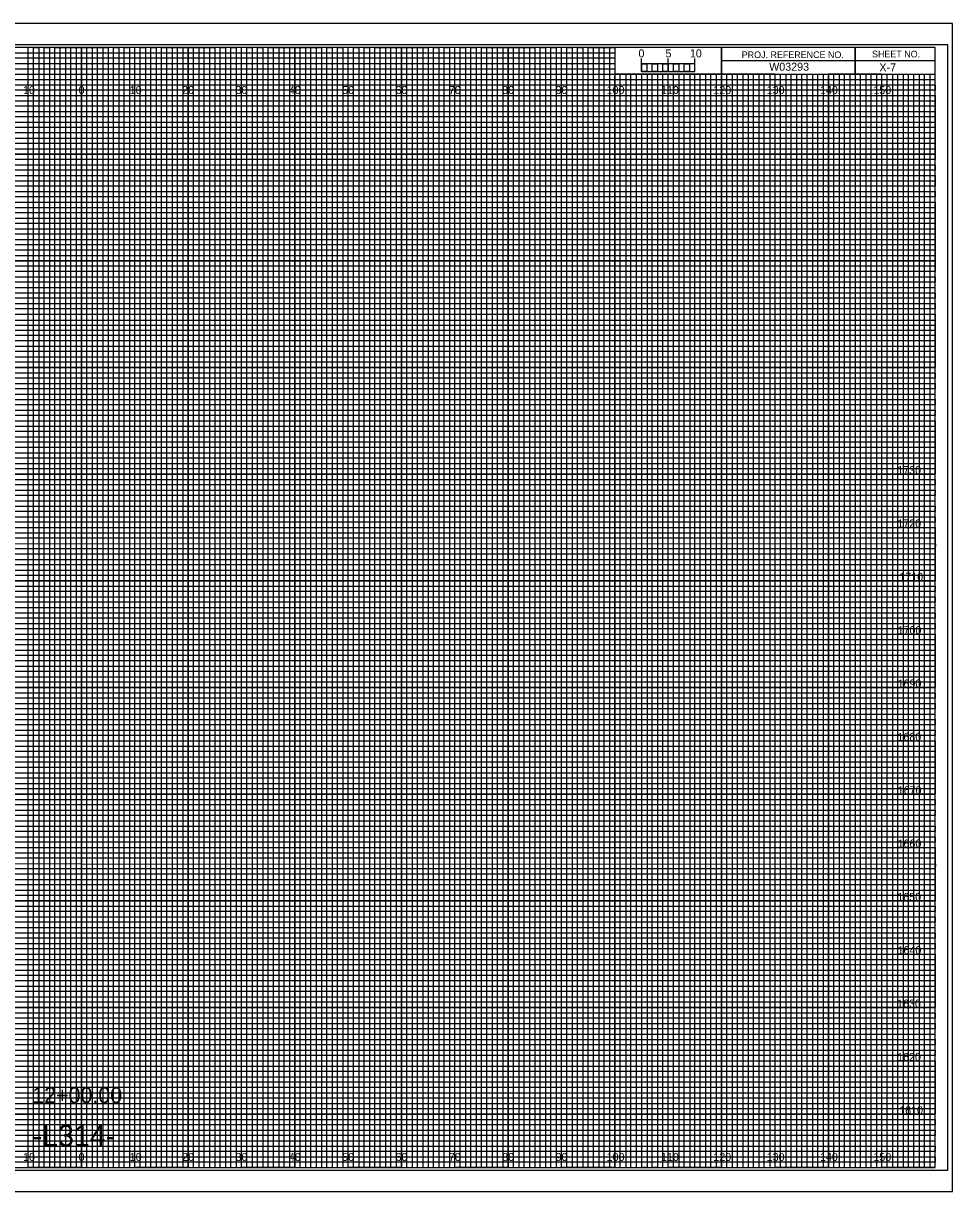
# Model space of a CAD drawing. Extents: x -13 to 323, y 435 to 654.
# Drawn here: x 149.1 to 323.3, y 435.5 to 654.5 of the extents above; entities that cross this region are included whole.
import ezdxf

# ---------------------------------------------------------------- set-up
doc = ezdxf.new("R2010")
doc.units = 0
for name, color, linetype in [('Exist Cross Section Cell', 7, 'Continuous'), ('Exist Horizontal Alignment', 7, 'Continuous'), ('Exist XS Center Line Elevation Label', 7, 'Continuous'), ('Exist XS Ground Line', 7, 'Continuous'), ('Prop Study Area', 7, 'Continuous'), ('Prop XS Finish Grade', 7, 'Continuous'), ('Prop XS Finish Grade Earthwork', 7, 'Continuous'), ('Prop XS Finish Grade Pavement', 7, 'Continuous'), ('Prop XS Pvmt Edge Slope', 7, 'Continuous'), ('Prop XS SE Text', 7, 'Continuous'), ('Prop XS Side Slope Text', 7, 'Continuous'), ('Prop XS Subgrade Earthwork', 7, 'Continuous'), ('Prop XSC Text', 7, 'Continuous'), ('Scratch_Level_0', 7, 'Continuous'), ('Scratch_Level_5', 7, 'Continuous'), ('Typical Guardrail CELL', 7, 'Continuous')]:
    doc.layers.add(name, color=color, linetype=linetype)

msp = doc.modelspace()

# ---------------------------------------------------------------- linework, layer by layer
at = {"layer": 'Exist Cross Section Cell'}
for p, q in [((265, 645.49), (265, 647.9)), ((265, 646.9), (265, 647.9)), ((270, 645.49), (270, 647.9)), ((275, 645.49), (275, 647.9)), ((275, 646.9), (275, 647.9))]:
    msp.add_line(p, q, dxfattribs=at)
for points in [[(275, 646.9), (265, 646.9), (265, 645.49), (275, 645.49)], [(265, 646.9), (266, 646.9), (266, 645.49), (265, 645.49)], [(267, 646.9), (268, 646.9), (268, 645.49), (267, 645.49)], [(269, 646.9), (270, 646.9), (270, 645.49), (269, 645.49)], [(271, 646.9), (272, 646.9), (272, 645.49), (271, 645.49)], [(273, 646.9), (274, 646.9), (274, 645.49), (273, 645.49)]]:
    msp.add_lwpolyline(points, close=True, dxfattribs=at)
at = {"layer": 'Exist Horizontal Alignment'}
for points in [[(145, 440), (155, 440), (155, 650), (165, 650), (165, 440), (175, 440), (175, 650), (185, 650), (185, 440), (195, 440), (195, 650), (205, 650), (205, 440), (215, 440), (215, 650), (225, 650), (225, 440), (235, 440), (235, 650), (245, 650), (245, 440), (255, 440), (255, 650), (259.93, 650), (260, 650), (260, 645), (264.99, 645), (264.99, 440), (275, 440), (275, 645), (285, 645), (285, 440), (295, 440), (295, 645), (305, 645), (305, 440), (315, 440), (315, 645)], [(0, 645), (275, 645)], [(0, 625), (320, 625), (320, 635), (0, 635)], [(0, 605), (320, 605), (320, 615), (0, 615)], [(0, 585), (320, 585), (320, 595), (0, 595)], [(0, 565), (320, 565), (320, 575), (0, 575)], [(0, 545), (320, 545), (320, 555), (0, 555)], [(0, 525), (320, 525), (320, 535), (0, 535)], [(0, 505), (320, 505), (320, 515), (0, 515)], [(0, 485), (320, 485), (320, 495), (0, 495)], [(0, 465), (320, 465), (320, 475), (0, 475)], [(0, 445), (320, 445), (320, 455), (0, 455)]]:
    msp.add_lwpolyline(points, dxfattribs=at)
at = {"layer": 'Exist XS Center Line Elevation Label'}
for p, q in [((267, 645), (266.01, 645)), ((266.01, 645), (266.01, 440)), ((267, 440), (267, 645)), ((269, 645), (268, 645)), ((268, 645), (268, 440)), ((269, 440), (269, 645)), ((266.01, 440), (265, 440)), ((268, 440), (267, 440))]:
    msp.add_line(p, q, dxfattribs=at)
for points in [[(150, 440), (151, 440), (151, 650), (152, 650), (152, 440)], [(152, 440), (153, 440), (153, 650), (154, 650), (154, 440)], [(155, 440), (156, 440), (156, 650), (157, 650), (157, 440)], [(157, 440), (158, 440), (158, 650), (159, 650), (159, 440)], [(160, 440), (161, 440), (161, 650), (162, 650), (162, 440)], [(162, 440), (163, 440), (163, 650), (164, 650), (164, 440)], [(165, 440), (166, 440), (166, 650), (167, 650), (167, 440)], [(167, 440), (168, 440), (168, 650), (169, 650), (169, 440)], [(170, 440), (171, 440), (171, 650), (172, 650), (172, 440)], [(172, 440), (173, 440), (173, 650), (174, 650), (174, 440)], [(175, 440), (176, 440), (176, 650), (177, 650), (177, 440)], [(177, 440), (178, 440), (178, 650), (179, 650), (179, 440)], [(180, 440), (181, 440), (181, 650), (182, 650), (182, 440)], [(182, 440), (183, 440), (183, 650), (184, 650), (184, 440)], [(185, 440), (186, 440), (186, 650), (187, 650), (187, 440)], [(187, 440), (188, 440), (188, 650), (189, 650), (189, 440)], [(190, 440), (191, 440), (191, 650), (192, 650), (192, 440)], [(192, 440), (193, 440), (193, 650), (194, 650), (194, 440)], [(195, 440), (196, 440), (196, 650), (197, 650), (197, 440)], [(197, 440), (198, 440), (198, 650), (199, 650), (199, 440)], [(200, 440), (201, 440), (201, 650), (202, 650), (202, 440)], [(202, 440), (203, 440), (203, 650), (204, 650), (204, 440)], [(205, 440), (206, 440), (206, 650), (207, 650), (207, 440)], [(207, 440), (208, 440), (208, 650), (209, 650), (209, 440)], [(210, 440), (211, 440), (211, 650), (212, 650), (212, 440)], [(212, 440), (213, 440), (213, 650), (214, 650), (214, 440)], [(215, 440), (216, 440), (216, 650), (217, 650), (217, 440)], [(217, 440), (218, 440), (218, 650), (219, 650), (219, 440)], [(220, 440), (221, 440), (221, 650), (222, 650), (222, 440)], [(222, 440), (223, 440), (223, 650), (224, 650), (224, 440)], [(225, 440), (226, 440), (226, 650), (227, 650), (227, 440)], [(227, 440), (228, 440), (228, 650), (229, 650), (229, 440)], [(230, 440), (231, 440), (231, 650), (232, 650), (232, 440)], [(232, 440), (233, 440), (233, 650), (234, 650), (234, 440)], [(235, 440), (236, 440), (236, 650), (237, 650), (237, 440)], [(237, 440), (238, 440), (238, 650), (239, 650), (239, 440)], [(240, 440), (241, 440), (241, 650), (242, 650), (242, 440)], [(242, 440), (243, 440), (243, 650), (244, 650), (244, 440)], [(245, 440), (246, 440), (246, 650), (247, 650), (247, 440)], [(247, 440), (248, 440), (248, 650), (249, 650), (249, 440)], [(250, 440), (251, 440), (251, 650), (252, 650), (252, 440)], [(252, 440), (253, 440), (253, 650), (254, 650), (254, 440)], [(255, 440), (256, 440), (256, 650), (257, 650), (257, 440)], [(257, 440), (258, 440), (258, 650), (259, 650), (259, 440)], [(260, 440), (261, 440), (261, 645), (262.02, 645), (262.02, 440)], [(262, 440), (263, 440), (263, 645), (263.99, 645), (263.99, 440)], [(270, 440), (270.98, 440), (270.98, 645), (272, 645), (272, 440)], [(272, 440), (273, 440), (273, 645), (274.05, 645), (274.05, 440)], [(275, 440), (276, 440), (276, 645), (277, 645), (277, 440)], [(277, 440), (278, 440), (278, 645), (279, 645), (279, 440)], [(280, 440), (281, 440), (281, 645), (282, 645), (282, 440)], [(282, 440), (283, 440), (283, 645), (284, 645), (284, 440)], [(285, 440), (286, 440), (286, 645), (287, 645), (287, 440)], [(287, 440), (288, 440), (288, 645), (289, 645), (289, 440)], [(290, 440), (291, 440), (291, 645), (292, 645), (292, 440)], [(292, 440), (293, 440), (293, 645), (294, 645), (294, 440)], [(295, 440), (296, 440), (296, 645), (297, 645), (297, 440)], [(297, 440), (298, 440), (298, 645), (299, 645), (299, 440)], [(300, 440), (301, 440), (301, 645), (302, 645), (302, 440)], [(302, 440), (303, 440), (303, 645), (304, 645), (304, 440)], [(305, 440), (306, 440), (306, 645), (307, 645), (307, 440)], [(307, 440), (308, 440), (308, 645), (309, 645), (309, 440)], [(310, 440), (311, 440), (311, 645), (312, 645), (312, 440)], [(312, 440), (313, 440), (313, 645), (314, 645), (314, 440)], [(315, 440), (316, 440), (316, 645), (317, 645), (317, 440)], [(317, 440), (318, 440), (318, 645), (319, 645), (319, 440)]]:
    msp.add_lwpolyline(points, dxfattribs=at)
at = {"layer": 'Exist XS Ground Line'}
for p, q in [((305, 650), (305, 645)), ((305, 645), (305, 650)), ((280, 647.5), (280, 645)), ((320, 647.49), (280, 647.49)), ((280, 645), (320, 645))]:
    msp.add_line(p, q, dxfattribs=at)
for points in [[(320, 650), (0, 650), (0, 440), (320, 440)], [(280, 650), (260, 650), (260, 645.03), (280, 645.03)], [(320, 650), (280, 650), (280, 645), (320, 645)]]:
    msp.add_lwpolyline(points, close=True, dxfattribs=at)
at = {"layer": 'Prop XS Finish Grade'}
msp.add_lwpolyline([(-10.8, 439.5), (322.4, 439.5), (322.4, 650.5), (-10.8, 650.5)], close=True, dxfattribs=at)
at = {"layer": 'Prop XS Finish Grade Pavement'}
msp.add_lwpolyline([(-13.4, 435.5), (323.3, 435.5), (323.3, 654.5), (-13.4, 654.5)], close=True, dxfattribs=at)
at = {"layer": 'Prop XS Pvmt Edge Slope'}
for p, q in [((323.3, 654.5), (-13.4, 654.5)), ((-13.4, 435.5), (323.3, 435.5))]:
    msp.add_line(p, q, dxfattribs=at)
at = {"layer": 'Scratch_Level_0'}
for p, q in [((150, 650), (140, 650)), ((150, 440), (150, 650)), ((170, 650), (160, 650)), ((160, 650), (160, 440)), ((170, 440), (170, 650)), ((190, 650), (180, 650)), ((180, 650), (180, 440)), ((190, 440), (190, 650)), ((210, 650), (200, 650)), ((200, 650), (200, 440)), ((210, 440), (210, 650)), ((230, 650), (220, 650)), ((220, 650), (220, 440)), ((230, 440), (230, 650)), ((250, 650), (240, 650)), ((240, 650), (240, 440)), ((250, 440), (250, 650)), ((260, 650), (260, 440)), ((270, 440), (270, 645)), ((290, 645), (280, 645)), ((280, 645), (280, 440)), ((290, 440), (290, 645)), ((310, 645), (300, 645)), ((300, 645), (300, 440)), ((310, 440), (310, 645)), ((160, 440), (150, 440)), ((180, 440), (170, 440)), ((200, 440), (190, 440)), ((220, 440), (210, 440)), ((240, 440), (230, 440)), ((260, 440), (250, 440)), ((280, 440), (270, 440)), ((300, 440), (290, 440)), ((320, 440), (310, 440)), ((320, 440), (320, 440))]:
    msp.add_line(p, q, dxfattribs=at)
for points in [[(0, 640), (320, 640), (320, 630), (0, 630)], [(0, 620), (320, 620), (320, 610), (0, 610)], [(0, 600), (320, 600), (320, 590), (0, 590)], [(0, 580), (320, 580), (320, 570), (0, 570)], [(0, 560), (320, 560), (320, 550), (0, 550)], [(0, 540), (320, 540), (320, 530), (0, 530)], [(0, 520), (320, 520), (320, 510), (0, 510)], [(0, 500), (320, 500), (320, 490), (0, 490)], [(0, 480), (320, 480), (320, 470), (0, 470)], [(0, 460), (320, 460), (320, 450), (0, 450)]]:
    msp.add_lwpolyline(points, dxfattribs=at)
at = {"layer": 'Scratch_Level_5'}
for p, q in [((0, 649), (260, 649)), ((260, 649), (260, 647.98)), ((260, 647.98), (0, 647.98)), ((0, 647), (260, 647)), ((260, 647), (260, 645.89)), ((260, 645.89), (0, 645.89)), ((0, 644), (320, 644))]:
    msp.add_line(p, q, dxfattribs=at)
for points in [[(0, 643), (270, 643), (320, 643), (320, 642), (0, 642)], [(0, 641), (320, 641), (320, 639), (0, 639)], [(0, 638), (320, 638), (320, 637), (0, 636.98)], [(0, 636), (320, 636), (320, 634), (0, 634)], [(0, 633), (320, 633), (320, 632), (0, 632)], [(0, 631), (320, 631), (320, 629), (0, 629)], [(0, 628), (320, 628), (320, 627), (0, 627)], [(0, 626), (320, 626), (320, 624), (0, 624)], [(0, 623), (320, 623), (320, 622), (0, 622)], [(0, 621), (320, 621), (320, 619), (0, 619)], [(0, 618), (320, 618), (320, 617), (0, 617)], [(0, 616), (320, 616), (320, 613.95), (320, 613), (320, 612), (0, 612)], [(0, 614), (320, 614), (320, 613), (0, 613)], [(0, 611), (320, 611), (320, 609), (0, 609.03)], [(0, 609.03), (320, 609), (320, 608), (0, 608)], [(0, 607), (320, 607), (320, 606), (0, 606)], [(0, 604), (320, 604), (320, 603), (0, 603)], [(0, 602), (320, 602), (320, 601), (0, 601)], [(-0.07, 598.89), (320, 598.89), (320, 597.88), (-0.07, 597.88)], [(0, 597), (320, 597), (320, 596), (0, 596)], [(0, 594), (320, 594), (320, 593), (0, 593)], [(0, 592), (320, 592), (320, 591), (0, 591)], [(0, 589), (320, 589), (320, 588), (0, 588)], [(0, 587), (320, 587), (320, 586), (0, 586)], [(0, 584), (320, 584), (320, 583), (0, 583)], [(0, 582), (320, 582), (320, 581), (0, 581)], [(0, 579), (320, 579), (319.99, 577.98), (0, 578)], [(0, 577), (320, 577), (320, 576), (0, 576)], [(0, 574), (320, 574), (320, 573), (0, 573)], [(0, 572), (320, 572), (320, 571), (0, 571)], [(0, 569), (320, 569), (320, 568), (0, 568)], [(0, 567), (320, 567), (320, 566), (0, 566)], [(0, 564), (320, 564), (320, 563), (0, 563)], [(0, 562), (320, 562), (320, 561), (0, 561)], [(0, 559), (320, 559), (320, 558), (0, 558)], [(0, 556.99), (320.07, 556.91), (320, 556), (0, 556)], [(0, 554), (320, 554), (320, 553), (0, 553)], [(0, 552), (320, 552), (320, 551), (0, 551)], [(0, 549), (320, 549), (320, 548), (0, 548)], [(0, 547), (320, 547), (320, 546), (0, 546)], [(0, 544), (320, 544), (320, 543), (0, 543)], [(0, 542), (320, 542), (320, 541), (0, 541)], [(0, 539), (320, 539), (320, 538), (0, 538)], [(0, 537), (320, 537), (320, 536), (0, 536)], [(0, 534), (320, 534), (320, 533), (0, 533)], [(0, 532), (320, 532), (320, 531), (0, 531)], [(0, 529), (320, 529), (320, 528), (0, 528)], [(0, 527), (320, 527), (320, 526), (0, 526)], [(0, 524), (320, 524), (320, 523), (0, 523)], [(0, 522), (320, 522), (320, 521), (0, 521)], [(0, 519), (320, 519), (319.99, 517.98), (0, 518)], [(0, 517), (320, 517), (320, 516), (0, 516)], [(0, 514), (320, 514), (320, 513), (0, 513)], [(0, 512), (320, 512), (320, 511), (0, 511)], [(0, 509), (320, 509), (320, 508), (0, 508)], [(0, 507), (320, 507), (320, 506), (0, 506)], [(0, 504), (320, 504), (320, 503), (0, 503)], [(0, 502), (320, 502), (320, 501), (0, 501)], [(0, 499), (320, 499), (320, 498), (0, 498)], [(0, 496.99), (320.07, 496.91), (320, 496), (0, 496)], [(0, 494), (320, 494), (320, 493), (0, 493)], [(0, 492), (320, 492), (320, 491), (0, 491)], [(0, 489), (320, 489), (320, 488), (0, 488)], [(0, 487), (320, 487), (320, 486), (0, 486)], [(0, 484), (320, 484), (320, 483), (0, 483)], [(0, 482), (320, 482), (320, 481), (0, 481)], [(0, 479), (320, 479), (320, 478), (0, 478)], [(0, 477), (320, 477), (320, 476), (0, 476)], [(0, 474), (320, 474), (320, 473), (0, 473)], [(0, 472), (320, 472), (320, 471), (0, 471)], [(0, 469), (320, 469), (320, 468), (0, 468)], [(0, 467), (320, 467), (320, 466), (0, 466)], [(0, 464), (320, 464), (320, 463), (0, 463)], [(0, 462), (320, 462), (320, 461), (0, 461)], [(0, 459), (320, 459), (320, 458), (0, 458)], [(0, 457), (320, 457), (320, 456), (0, 456)], [(0, 454), (320, 454), (320, 453), (0, 453)], [(0, 452), (320, 452), (320, 451), (0, 451)], [(0, 449), (320, 449), (320, 448), (0, 448)], [(0, 447), (320, 447), (320, 446), (0, 446)], [(0, 444), (320, 444), (320, 443), (0, 443)], [(0, 442), (320, 442), (320, 441), (0, 441)]]:
    msp.add_lwpolyline(points, dxfattribs=at)
at = {"layer": 'Typical Guardrail CELL'}
for p, q in [((150, 440), (150, 650)), ((160, 440), (160, 650)), ((170, 440), (170, 650)), ((180, 440), (180, 650)), ((190, 440), (190, 650)), ((200, 440), (200, 650)), ((210, 440), (210, 650)), ((220, 440), (220, 650)), ((230, 440), (230, 650)), ((240, 440), (240, 650)), ((250, 440), (250, 650)), ((260, 440), (260, 644.69)), ((270, 440), (270, 644.69)), ((280, 440), (280, 644.69)), ((290, 440), (290, 644.69)), ((300, 440), (300, 644.69)), ((310, 440), (310, 644.69)), ((0, 640), (320, 640)), ((0, 630), (320, 630)), ((0, 620), (320, 620)), ((0, 610), (320, 610)), ((0, 600), (320, 600)), ((0, 590), (320, 590)), ((0, 580), (320, 580)), ((0, 570), (320, 570)), ((0, 560), (320, 560)), ((0, 550), (320, 550)), ((0, 540), (320, 540)), ((0, 530), (320, 530)), ((0, 520), (320, 520)), ((0, 510), (320, 510)), ((0, 500), (320, 500)), ((0, 490), (320, 490)), ((0, 480), (320, 480)), ((0, 470), (320, 470)), ((0, 460), (320, 460)), ((0, 450), (320, 450))]:
    msp.add_line(p, q, dxfattribs=at)

# ---------------------------------------------------------------- texts
at = {"layer": 'Exist Cross Section Cell'}
msp.add_text('0', height=1.5, dxfattribs=at).set_placement((264.41, 648.12))
at = {"layer": 'Exist XS Ground Line'}
for s, p in [('PROJ. REFERENCE NO.', (283.77, 647.99)), ('SHEET NO.', (308.19, 648.12))]:
    msp.add_text(s, height=1.25, dxfattribs=at).set_placement(p)
at = {"layer": 'Prop Study Area'}
for s, p in [('10', (149.04, 641.25)), ('0', (159.45, 641.25)), ('0', (159.45, 641.25)), ('10', (169.04, 641.25)), ('20', (178.86, 641.25)), ('30', (188.86, 641.25)), ('40', (198.86, 641.25)), ('50', (208.86, 641.25)), ('60', (218.86, 641.25)), ('70', (228.86, 641.25)), ('80', (238.86, 641.25)), ('90', (248.86, 641.25)), ('100', (258.44, 641.25)), ('110', (268.62, 641.25)), ('120', (278.44, 641.25)), ('130', (288.44, 641.25)), ('140', (298.44, 641.25)), ('150', (308.44, 641.25)), ('10', (149.04, 441.25)), ('0', (159.45, 441.25)), ('0', (159.45, 441.25)), ('10', (169.04, 441.25)), ('20', (178.86, 441.25)), ('30', (188.86, 441.25)), ('40', (198.86, 441.25)), ('50', (208.86, 441.25)), ('60', (218.86, 441.25)), ('70', (228.86, 441.25)), ('80', (238.86, 441.25)), ('90', (248.86, 441.25)), ('100', (258.44, 441.25)), ('110', (268.62, 441.25)), ('120', (278.44, 441.25)), ('130', (288.44, 441.25)), ('140', (298.44, 441.25)), ('150', (308.44, 441.25))]:
    msp.add_text(s, height=1.5, dxfattribs=at).set_placement(p)
at = {"layer": 'Prop XS Finish Grade Earthwork'}
msp.add_text('12+00.00', height=3, dxfattribs=at).set_placement((150.77, 452.1))
at = {"layer": 'Prop XS SE Text'}
msp.add_text('-L314-', height=4, dxfattribs=at).set_placement((150.84, 444))
at = {"layer": 'Prop XS Side Slope Text'}
for s, p in [('W03293', (288.91, 645.62)), ('X-7', (309.57, 645.5))]:
    msp.add_text(s, height=1.5, dxfattribs=at).set_placement(p)
at = {"layer": 'Prop XS Subgrade Earthwork'}
for s, p in [('1730', (312.92, 570)), ('1720', (312.93, 560)), ('1710', (313.31, 550)), ('1700', (312.98, 540)), ('1690', (312.97, 530)), ('1680', (312.95, 520)), ('1670', (313, 510)), ('1660', (312.97, 500)), ('1650', (312.92, 490)), ('1640', (312.97, 480)), ('1630', (312.89, 470)), ('1620', (312.9, 460)), ('1610', (313.28, 450))]:
    msp.add_text(s, height=1.5, dxfattribs=at).set_placement(p)
at = {"layer": 'Prop XSC Text'}
for s, p in [('5', (269.47, 648.12)), ('10', (274.04, 648.12))]:
    msp.add_text(s, height=1.5, dxfattribs=at).set_placement(p)

doc.saveas('drawing.dxf')
